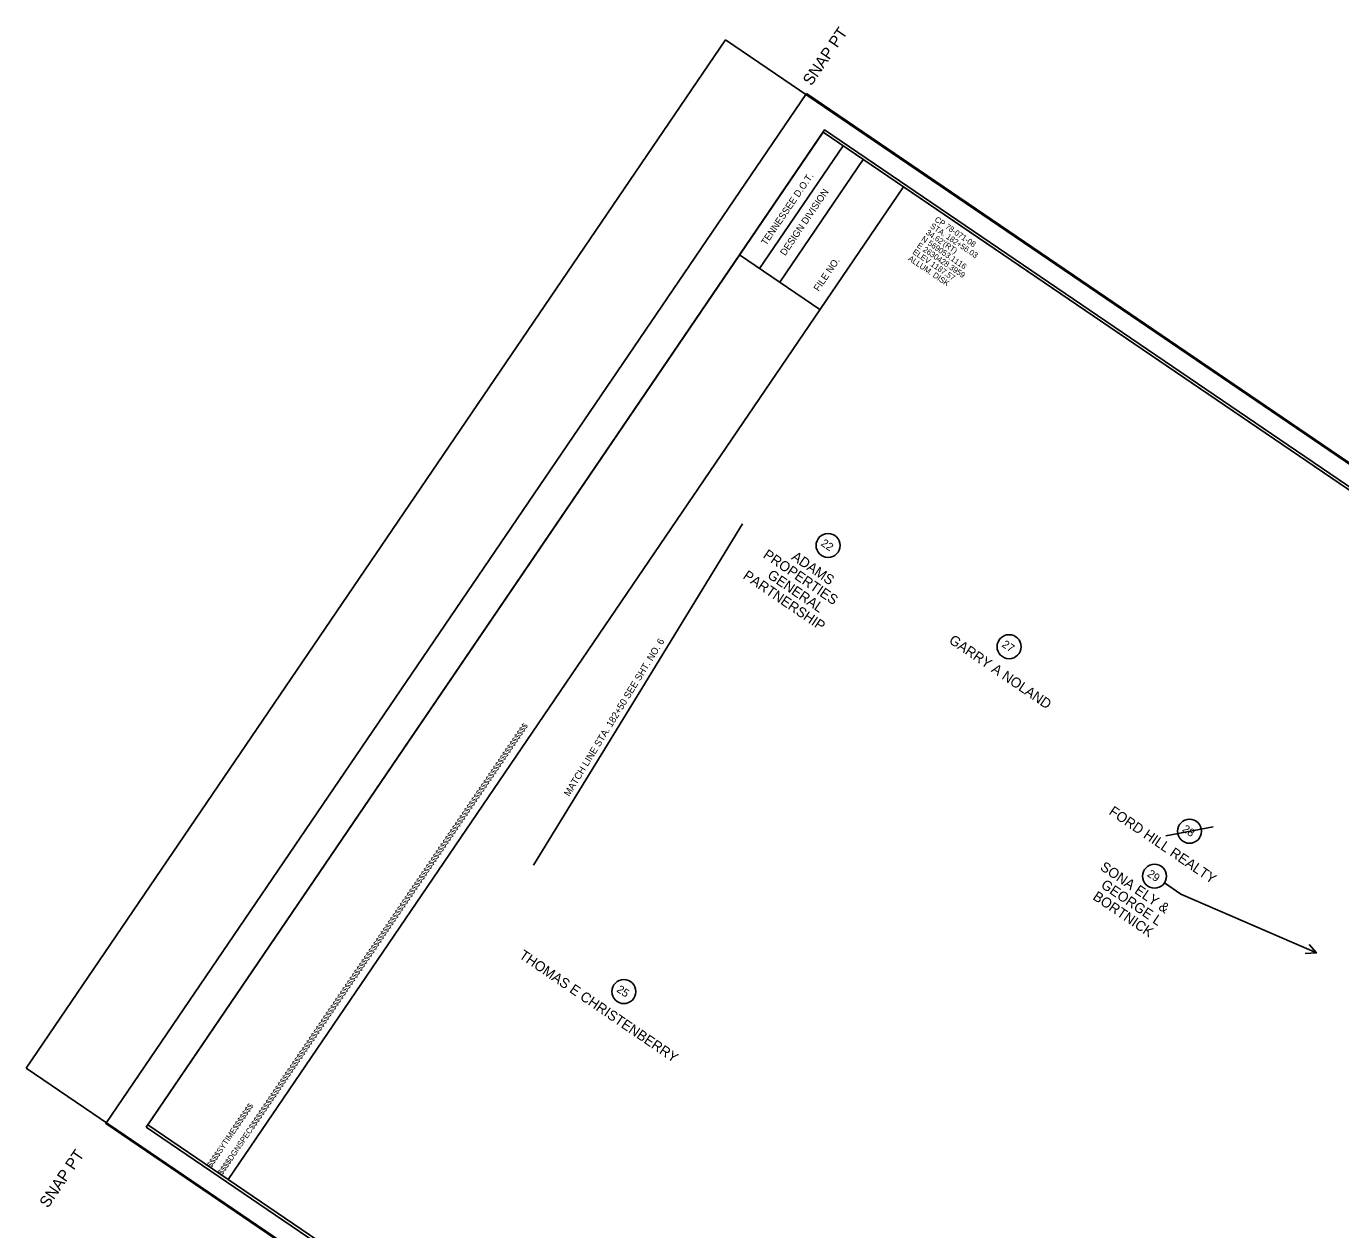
# Model space of a CAD drawing. Extents: x 2629906 to 2632029, y 567681 to 569670.
# Drawn here: x 2629906 to 2631056, y 568618 to 569670 of the extents above; entities that cross this region are included whole.
import ezdxf

# ---------------------------------------------------------------- set-up
doc = ezdxf.new("R2010")
doc.units = 0
for name, color, linetype in [('DESIGN - CENTERLINE - Proposed Text', 7, 'Continuous'), ('DESIGN - SCRATCH - User 1', 7, 'Continuous'), ('DESIGN - SHEET - Corner Text', 7, 'Continuous'), ('DESIGN - SHEET - Light Grid', 7, 'Continuous'), ('DESIGN - SHEET - Linework', 7, 'Continuous'), ('DESIGN - SHEET - Plot Shape', 7, 'Continuous'), ('SURVEY - CONTROL with Text', 7, 'Continuous'), ('SURVEY - PROPERTY - Owners', 7, 'Continuous'), ('SURVEY - PROPERTY - Tract Numbers', 7, 'Continuous')]:
    doc.layers.add(name, color=color, linetype=linetype)

msp = doc.modelspace()

# ---------------------------------------------------------------- linework, layer by layer
at = {"layer": 'DESIGN - CENTERLINE - Proposed Text'}
msp.add_lwpolyline([(2630349.9, 568936.6), (2630441.4, 569085.8), (2630532.9, 569234.9)], dxfattribs=at)
at = {"layer": 'DESIGN - SCRATCH - User 1'}
msp.add_line((2630419.6, 569067.6), (2630419.6, 569067.6), dxfattribs=at)
at = {"layer": 'DESIGN - SHEET - Light Grid'}
msp.add_lwpolyline([(2630011.2, 568707.4), (2631387.9, 567770.9), (2631981.3, 568643.2), (2630604.6, 569579.7)], close=True, dxfattribs=at)
at = {"layer": 'DESIGN - SHEET - Linework'}
for p, q in [((2629906.4, 568759.1), (2630518, 569658.2)), ((2630518, 569658.2), (2632006.3, 568645.8)), ((2630620.8, 569565.7), (2630547.7, 569458.3)), ((2630638.4, 569553.7), (2630565.3, 569446.3)), ((2629906.4, 568759.1), (2631394.7, 567746.7))]:
    msp.add_line(p, q, dxfattribs=at)
for points in [[(2630673.6, 569529.8), (2630603.2, 569577.6), (2630530.2, 569470.2), (2630600.5, 569422.4)], [(2630673.6, 569529.8), (2630083, 568661.6), (2631384.6, 567776.2), (2631975.1, 568644.4), (2630673.6, 569529.8)]]:
    msp.add_lwpolyline(points, dxfattribs=at)
at = {"layer": 'DESIGN - SHEET - Plot Shape'}
for points in [[(2630588.8, 569611.3), (2631994.4, 568655.1), (2631381.6, 567754.4), (2629976, 568710.6)], [(2630603.2, 569577.6), (2631975.1, 568644.4), (2631384.6, 567776.2), (2630012.6, 568709.5)]]:
    msp.add_lwpolyline(points, close=True, dxfattribs=at)
at = {"layer": 'SURVEY - PROPERTY - Tract Numbers'}
msp.add_line((2630903.1, 568962.2), (2630944.3, 568970.1), dxfattribs=at)
for points in [[(2630916.2, 568911.1), (2630901.8, 568921)], [(2631034.7, 568859.8), (2630916.2, 568911.1)], [(2631028.4, 568867.3), (2631034.7, 568859.8), (2631024.9, 568859.3)]]:
    msp.add_lwpolyline(points, dxfattribs=at)
for centre in [(2630607.6, 569216.1), (2630765.9, 569127.6), (2630923.7, 568966.2), (2630893.1, 568926.9), (2630429, 568826)]:
    msp.add_circle(centre, 10.5, dxfattribs=at)

# ---------------------------------------------------------------- texts
at = {"layer": 'DESIGN - CENTERLINE - Proposed Text'}
msp.add_text('MATCH LINE STA. 182+50 SEE SHT. NO. 6', height=6, rotation=58.4832, dxfattribs=at).set_placement((2630381.2, 568996.2))
at = {"layer": 'DESIGN - SHEET - Corner Text'}
for s, height, p in [('  SNAP PT', 10, (2630588.8, 569611.3)), ('TENNESSEE D.O.T.', 6, (2630553.4, 569478)), ('DESIGN DIVISION', 6, (2630570.1, 569469)), ('FILE NO.', 6, (2630599.4, 569437.8)), ('$$$$DGNSPEC$$$$$$$$$$$$$$$$$$$$$$$$$$$$$$$$$$$$$$$$$$$$$$$$$$$$$$$$$$$$$$$$$$$$$$$$$$$$$$$$$$$$$$$$$$$$$$$$$$$$$$$$$$$$$$$$$$$', 5.0001, (2630077.8, 568665.2)), ('$$$$SYTIME$$$$$$$', 5, (2630068.2, 568671.7)), ('SNAP PT  ', 10, (2629925.4, 568636.1))]:
    msp.add_text(s, height=height, rotation=55.7738, dxfattribs=at).set_placement(p)
at = {"layer": 'SURVEY - CONTROL with Text'}
for s, p in [("34.62'(RT)", (2630692.6, 569488.6)), ('STA. 182+56.03', (2630696.4, 569494.3)), ('CP 78-071-08', (2630700.3, 569500)), ('E 2630428.3959', (2630684.8, 569477.3)), ('N 569053.1116', (2630688.7, 569483)), ('ELEV 1187.57', (2630681, 569471.6)), ('ALLUM. DISK', (2630677.1, 569465.9))]:
    msp.add_text(s, height=5, rotation=325.7738, dxfattribs=at).set_placement(p)
at = {"layer": 'SURVEY - PROPERTY - Owners'}
for s, p in [('PROPERTIES', (2630550.1, 569206.1)), ('ADAMS', (2630574.8, 569204.4)), ('PARTNERSHIP', (2630532.5, 569187.8)), ('GENERAL', (2630553.8, 569188.4)), ('GARRY A NOLAND', (2630712.6, 569131.4)), ('FORD HILL REALTY', (2630852.5, 568981.6)), ('SONA ELY &', (2630844.8, 568933.1)), ('GEORGE L', (2630845.5, 568917.5)), ('BORTNICK', (2630838.4, 568907.2)), ('THOMAS E CHRISTENBERRY', (2630336.7, 568855.9))]:
    msp.add_text(s, height=8.75, rotation=325.7738, dxfattribs=at).set_placement(p)
at = {"layer": 'SURVEY - PROPERTY - Tract Numbers'}
for s, p in [('22', (2630600.7, 569216.6)), ('27', (2630759, 569128.1)), ('28', (2630916.7, 568966.7)), ('29', (2630886.1, 568927.4)), ('25', (2630422.1, 568826.4))]:
    msp.add_text(s, height=7, rotation=325.7738, dxfattribs=at).set_placement(p)

doc.saveas('drawing.dxf')
